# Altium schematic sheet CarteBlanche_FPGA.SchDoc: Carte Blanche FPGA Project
size A1; DrawnBy: SRKH; Engineer: SRKH; DocumentNumber: 1; Revision: CB500E; SheetNumber: 1; SheetTotal: 1
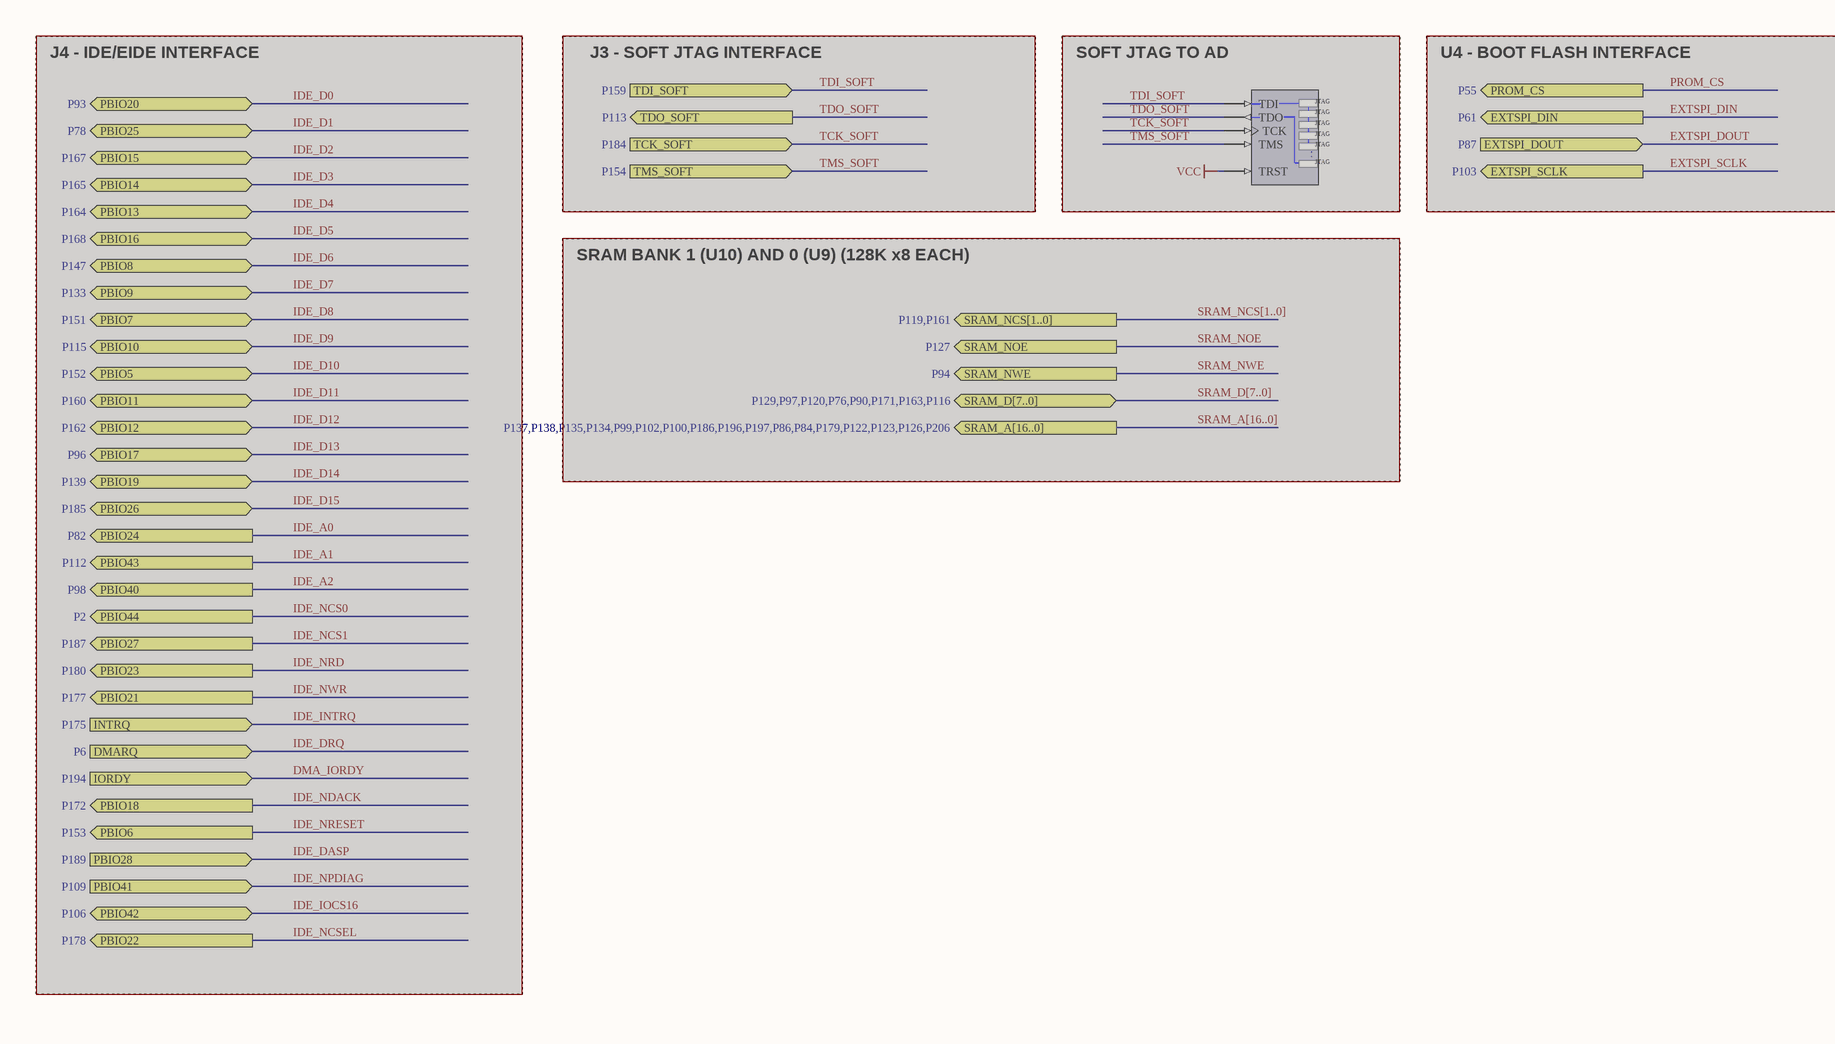
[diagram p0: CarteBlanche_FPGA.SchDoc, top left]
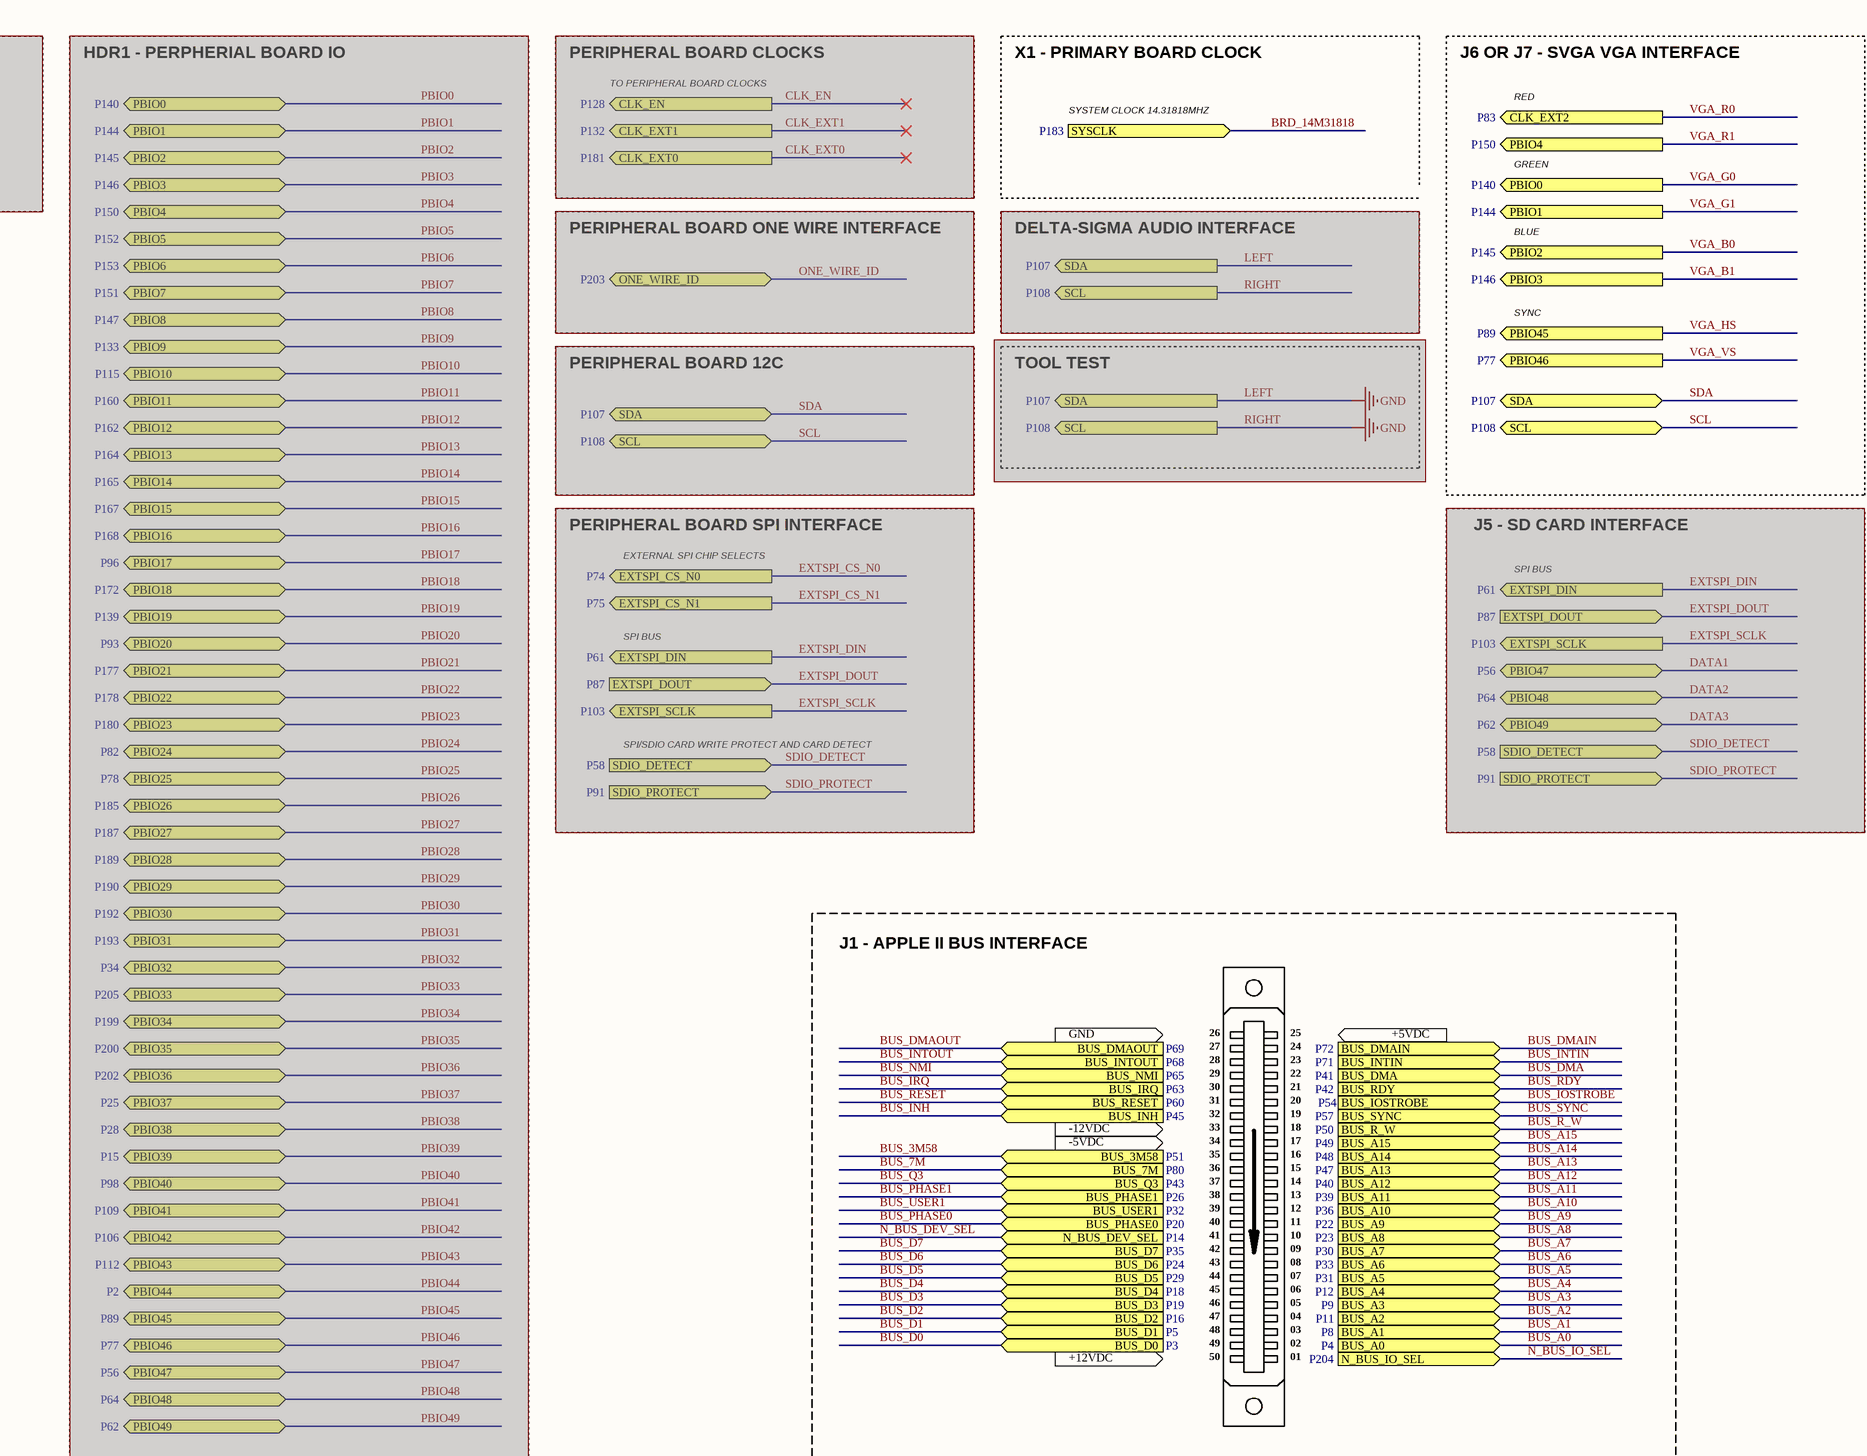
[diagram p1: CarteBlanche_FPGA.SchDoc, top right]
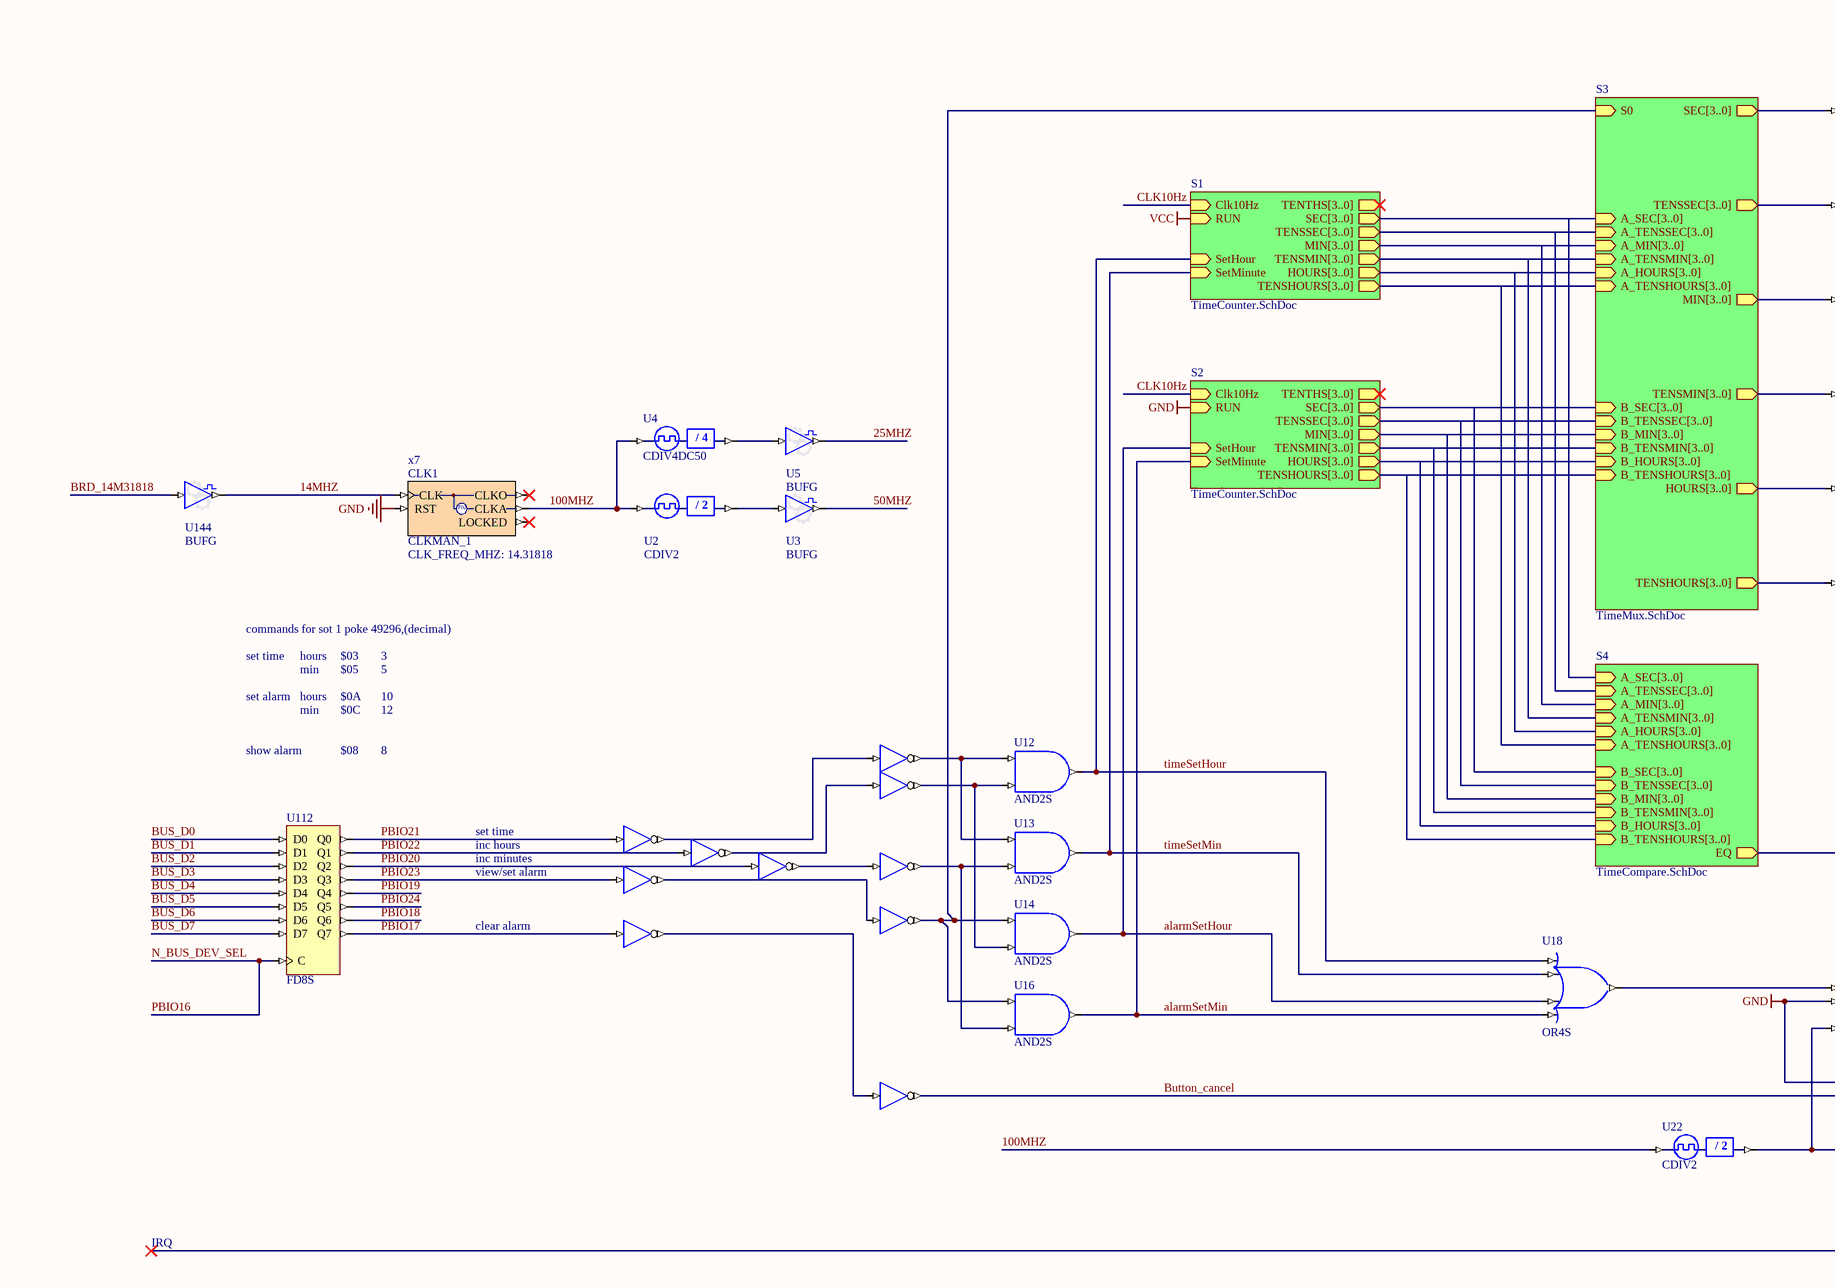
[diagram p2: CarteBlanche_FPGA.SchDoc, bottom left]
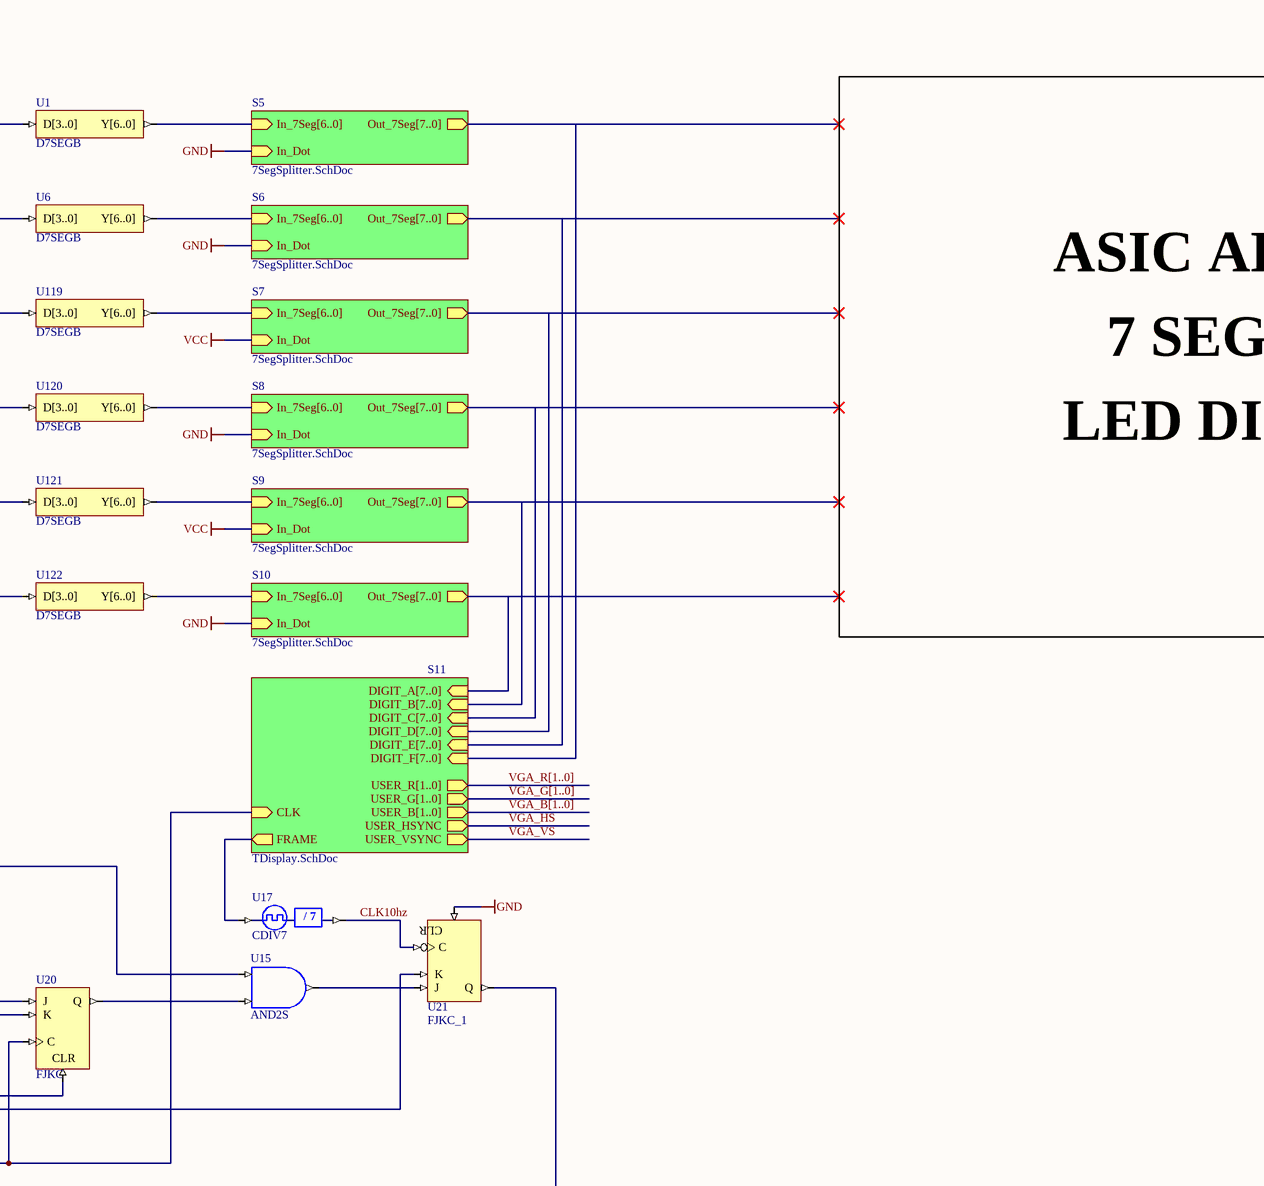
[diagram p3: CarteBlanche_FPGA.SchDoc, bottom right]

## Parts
CLK1  CLKMAN_1  CLK_FREQ_MHZ: 14.31818  ClkA_Operation: x7
NEXUS_JTAG_PORT  NEXUS_JTAG_PORT  (value not drawn)  (masked out: inside a compile mask, not in the netlist)
U1  D7SEGB
U2  CDIV2
U3  BUFG
U4  CDIV4DC50
U5  BUFG
U6  D7SEGB
U7  INV  (value not drawn)
U8  INV  (value not drawn)
U9  INV  (value not drawn)
U10  INV  (value not drawn)
U11  INV  (value not drawn)
U12  AND2S
U13  AND2S
U14  AND2S
U15  AND2S
U16  AND2S
U17  CDIV7
U18  OR4S
U19  INV  (value not drawn)
U20  FJKC
U21  FJKC_1
U22  CDIV2
U23  INV  (value not drawn)
U24  INV  (value not drawn)
U25  INV  (value not drawn)
U26  INV  (value not drawn)
U112  FD8S
U119  D7SEGB
U120  D7SEGB
U121  D7SEGB
U122  D7SEGB
U144  BUFG

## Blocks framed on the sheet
SOFT JTAG TO AD: NEXUS_JTAG_PORT

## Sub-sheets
S1 = TimeCounter.SchDoc: SetHour (in), SetMinute (in), Clk10Hz (in), SEC[3..0] (out), TENSSEC[3..0] (out), MIN[3..0] (out), TENSMIN[3..0] (out), HOURS[3..0] (out), TENSHOURS[3..0] (out), RUN (in), TENTHS[3..0] (out)
S2 = TimeCounter.SchDoc: SetHour (in), SetMinute (in), Clk10Hz (in), SEC[3..0] (out), TENSSEC[3..0] (out), MIN[3..0] (out), TENSMIN[3..0] (out), HOURS[3..0] (out), TENSHOURS[3..0] (out), RUN (in), TENTHS[3..0] (out)
S3 = TimeMux.SchDoc: SEC[3..0] (out), TENSSEC[3..0] (out), MIN[3..0] (out), TENSMIN[3..0] (out), HOURS[3..0] (out), TENSHOURS[3..0] (out), A_SEC[3..0] (in), A_TENSSEC[3..0] (in), A_MIN[3..0] (in), A_TENSMIN[3..0] (in), A_HOURS[3..0] (in), A_TENSHOURS[3..0] (in), B_SEC[3..0] (in), B_TENSSEC[3..0] (in), B_MIN[3..0] (in), B_TENSMIN[3..0] (in), B_HOURS[3..0] (in), B_TENSHOURS[3..0] (in), S0 (in)
S4 = TimeCompare.SchDoc: A_MIN[3..0] (in), A_TENSMIN[3..0] (in), A_HOURS[3..0] (in), A_TENSHOURS[3..0] (in), B_MIN[3..0] (in), B_TENSMIN[3..0] (in), B_HOURS[3..0] (in), B_TENSHOURS[3..0] (in), A_SEC[3..0] (in), A_TENSSEC[3..0] (in), B_SEC[3..0] (in), B_TENSSEC[3..0] (in), EQ (out)
S5 = 7SegSplitter.SchDoc: In_7Seg[6..0] (in), In_Dot (in), Out_7Seg[7..0] (out)
S6 = 7SegSplitter.SchDoc: In_7Seg[6..0] (in), In_Dot (in), Out_7Seg[7..0] (out)
S7 = 7SegSplitter.SchDoc: In_7Seg[6..0] (in), In_Dot (in), Out_7Seg[7..0] (out)
S8 = 7SegSplitter.SchDoc: In_7Seg[6..0] (in), In_Dot (in), Out_7Seg[7..0] (out)
S9 = 7SegSplitter.SchDoc: In_7Seg[6..0] (in), In_Dot (in), Out_7Seg[7..0] (out)
S10 = 7SegSplitter.SchDoc: In_7Seg[6..0] (in), In_Dot (in), Out_7Seg[7..0] (out)
S11 = TDisplay.SchDoc: CLK (in), FRAME (out), USER_R[1..0] (out), USER_G[1..0] (out), USER_B[1..0] (out), USER_HSYNC (out), USER_VSYNC (out), DIGIT_A[7..0] (in), DIGIT_B[7..0] (in), DIGIT_C[7..0] (in), DIGIT_D[7..0] (in), DIGIT_E[7..0] (in), DIGIT_F[7..0] (in)

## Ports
BUS_3M58 (in, see P51), BUS_7M (in, see P80), BUS_A0 (in, see P4), BUS_A1 (in, see P8), BUS_A2 (in, see P11), BUS_A3 (in, see P9), BUS_A4 (in, see P12), BUS_A5 (in, see P31), BUS_A6 (in, see P33), BUS_A7 (in, see P30), BUS_A8 (in, see P23), BUS_A9 (in, see P22), BUS_A10 (in, see P36), BUS_A11 (in, see P39), BUS_A12 (in, see P40), BUS_A13 (in, see P47), BUS_A14 (in, see P48), BUS_A15 (in, see P49), BUS_D0 (in, see P3), BUS_D1 (in, see P5), BUS_D2 (in, see P16), BUS_D3 (in, see P19), BUS_D4 (in, see P18), BUS_D5 (in, see P29), BUS_D6 (in, see P24), BUS_D7 (in, see P35), BUS_DMA (in, see P41), BUS_DMAIN (in, see P72), BUS_DMAOUT (in, see P69), BUS_INH (in, see P45), BUS_INTIN (in, see P71), BUS_INTOUT (in, see P68), BUS_IOSTROBE (in, see P54), BUS_IRQ (in, see P63), BUS_NMI (in, see P65), BUS_PHASE0 (in, see P20), BUS_PHASE1 (in, see P26), BUS_Q3 (in, see P43), BUS_R_W (in, see P50), BUS_RDY (in, see P42), BUS_RESET (in, see P60), BUS_SYNC (in, see P57), BUS_USER1 (in, see P32), CLK_EN (out, see P128), CLK_EXT0 (out, see P181), CLK_EXT1 (out, see P132), CLK_EXT2 (out, see P83), DMARQ (in, see P6), EXTSPI_CS_N0 (out, see P74), EXTSPI_CS_N1 (out, see P75), EXTSPI_DIN (out, see P61), EXTSPI_DOUT (in, see P87), EXTSPI_SCLK (out, see P103), INTRQ (in, see P175), IORDY (in, see P194), N_BUS_DEV_SEL (in, see P14), N_BUS_IO_SEL (in, see P204), ONE_WIRE_ID (bidir, see P203), PBIO0 (bidir, see P140), PBIO0 (out, see P140), PBIO1 (bidir, see P144), PBIO1 (out, see P144), PBIO2 (bidir, see P145), PBIO2 (out, see P145), PBIO3 (bidir, see P146), PBIO3 (out, see P146), PBIO4 (bidir, see P150), PBIO4 (out, see P150), PBIO5 (bidir, see P152), PBIO6 (bidir, see P153), PBIO6 (out, see P153), PBIO7 (bidir, see P151), PBIO8 (bidir, see P147), PBIO9 (bidir, see P133), PBIO10 (bidir, see P115), PBIO11 (bidir, see P160), PBIO12 (bidir, see P162), PBIO13 (bidir, see P164), PBIO14 (bidir, see P165), PBIO15 (bidir, see P167), PBIO16 (bidir, see P168), PBIO17 (bidir, see P96), PBIO18 (bidir, see P172), PBIO18 (out, see P172), PBIO19 (bidir, see P139), PBIO20 (bidir, see P93), PBIO21 (bidir, see P177), PBIO21 (out, see P177), PBIO22 (bidir, see P178), PBIO22 (out, see P178), PBIO23 (bidir, see P180), PBIO23 (out, see P180), PBIO24 (bidir, see P82), PBIO24 (out, see P82), PBIO25 (bidir, see P78), PBIO26 (bidir, see P185), PBIO27 (bidir, see P187), PBIO27 (out, see P187), PBIO28 (bidir, see P189), PBIO28 (in, see P189), PBIO29 (bidir, see P190), PBIO30 (bidir, see P192), PBIO31 (bidir, see P193), PBIO32 (bidir, see P34), PBIO33 (bidir, see P205), PBIO34 (bidir, see P199), PBIO35 (bidir, see P200), PBIO36 (bidir, see P202), PBIO37 (bidir, see P25), PBIO38 (bidir, see P28), PBIO39 (bidir, see P15), PBIO40 (bidir, see P98), PBIO40 (out, see P98), PBIO41 (bidir, see P109), PBIO41 (in, see P109), PBIO42 (bidir, see P106), PBIO43 (bidir, see P112), PBIO43 (out, see P112), PBIO44 (bidir, see P2), PBIO44 (out, see P2), PBIO45 (bidir, see P89), PBIO45 (out, see P89), PBIO46 (bidir, see P77), PBIO46 (out, see P77), PBIO47 (bidir, see P56), PBIO48 (bidir, see P64), PBIO49 (bidir, see P62), PROM_CS (out, see P55), SCL (bidir, see P108), SCL (out, see P108), SDA (bidir, see P107), SDA (out, see P107), SDIO_DETECT (in, see P58), SDIO_PROTECT (in, see P91), SRAM_A[16..0] (out, see P137,P138,P135,P134,P99,P102,P100,P186,P196,P197,P86,P84,P179,P122,P123,P126,P206), SRAM_D[7..0] (bidir, see P129,P97,P120,P76,P90,P171,P163,P116), SRAM_NCS[1..0] (out, see P119,P161), SRAM_NOE (out, see P127), SRAM_NWE (out, see P94), SYSCLK (in, see P183), TCK_SOFT (in, see P184), TDI_SOFT (in, see P159), TDO_SOFT (out, see P113), TMS_SOFT (in, see P154)

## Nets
GND: CLK1.RST U20.CLR U20.K U21.CLR ; sheet S2/RUN, sheet S5/In_Dot, sheet S6/In_Dot, sheet S8/In_Dot, sheet S10/In_Dot
VCC: sheet S1/RUN, sheet S7/In_Dot, sheet S9/In_Dot
14MHZ: CLK1.CLK U144.O
25MHZ: U5.O
50MHZ: U3.O
100MHZ: CLK1.CLKA U2.CLKIN U4.CLKIN U22.CLKIN
alarmSetHour: U14.O U18.I2 ; sheet S2/SetHour
alarmSetMin: U16.O U18.I3 ; sheet S2/SetMinute
BRD_14M31818: U144.I ; port SYSCLK
BUS_D0: U112.D0 ; port BUS_D0
BUS_D1: U112.D1 ; port BUS_D1
BUS_D2: U112.D2 ; port BUS_D2
BUS_D3: U112.D3 ; port BUS_D3
BUS_D4: U112.D4 ; port BUS_D4
BUS_D5: U112.D5 ; port BUS_D5
BUS_D6: U112.D6 ; port BUS_D6
BUS_D7: U112.D7 ; port BUS_D7
Button_cancel: U11.O U21.K
CLK10Hz: U17.CLKDV U21.C ; sheet S1/Clk10Hz, sheet S2/Clk10Hz
N_BUS_DEV_SEL: U112.C ; port N_BUS_DEV_SEL  [also labelled PBIO16]
PBIO17: U26.I U112.Q7
PBIO18: U112.Q6
PBIO19: U112.Q4
PBIO20: U24.I U112.Q2
PBIO21: U19.I U112.Q0
PBIO22: U23.I U112.Q1
PBIO23: U25.I U112.Q3
PBIO24: U112.Q5
timeSetHour: U12.O U18.I0 ; sheet S1/SetHour
timeSetMin: U13.O U18.I1 ; sheet S1/SetMinute
VGA_HS: port PBIO45, sheet S11/USER_HSYNC
VGA_VS: port PBIO46, sheet S11/USER_VSYNC
NetU2_CLKDV: U2.CLKDV U3.I
NetU4_CLKDV: U4.CLKDV U5.I
NetU7_I: U7.I U19.O
NetU7_O: U7.O U12.I0 U13.I0
NetU8_I: U8.I U23.O
NetU8_O: U8.O U12.I1 U14.I1
NetU9_I: U9.I U24.O
NetU9_O: U9.O U13.I1 U16.I1
NetU10_I: U10.I U25.O
NetU10_O: U10.O U14.I0 U16.I0 ; sheet S3/S0
NetU11_I: U11.I U26.O
NetU15_I0: U15.I0 ; sheet S4/EQ
NetU15_I1: U15.I1 U20.Q
NetU15_O: U15.O U21.J
NetU17_CLKIN: U17.CLKIN ; sheet S11/FRAME
NetU18_O: U18.O U20.J
NetU20_C: U20.C U22.CLKDV ; sheet S11/CLK

Not connected (* = marked no-connect by the designer): CLK1 CLKO* LOCKED*; U1 D[3..0] Y[6..0]; U6 D[3..0] Y[6..0]; U21 Q*; U119 D[3..0] Y[6..0]; U120 D[3..0] Y[6..0]; U121 D[3..0] Y[6..0]; U122 D[3..0] Y[6..0]

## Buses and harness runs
bus sheet S1/HOURS[3..0] = sheet S3/A_HOURS[3..0] = sheet S4/A_HOURS[3..0]
bus sheet S1/MIN[3..0] = sheet S3/A_MIN[3..0] = sheet S4/A_MIN[3..0]
bus sheet S1/SEC[3..0] = sheet S3/A_SEC[3..0] = sheet S4/A_SEC[3..0]
bus sheet S1/TENSHOURS[3..0] = sheet S3/A_TENSHOURS[3..0] = sheet S4/A_TENSHOURS[3..0]
bus sheet S1/TENSMIN[3..0] = sheet S3/A_TENSMIN[3..0] = sheet S4/A_TENSMIN[3..0]
bus sheet S1/TENSSEC[3..0] = sheet S3/A_TENSSEC[3..0] = sheet S4/A_TENSSEC[3..0]
bus sheet S2/HOURS[3..0] = sheet S3/B_HOURS[3..0] = sheet S4/B_HOURS[3..0]
bus sheet S2/MIN[3..0] = sheet S3/B_MIN[3..0] = sheet S4/B_MIN[3..0]
bus sheet S2/SEC[3..0] = sheet S3/B_SEC[3..0] = sheet S4/B_SEC[3..0]
bus sheet S2/TENSHOURS[3..0] = sheet S3/B_TENSHOURS[3..0] = sheet S4/B_TENSHOURS[3..0]
bus sheet S2/TENSMIN[3..0] = sheet S3/B_TENSMIN[3..0] = sheet S4/B_TENSMIN[3..0]
bus sheet S2/TENSSEC[3..0] = sheet S3/B_TENSSEC[3..0] = sheet S4/B_TENSSEC[3..0]
bus sheet S5/Out_7Seg[7..0] = sheet S11/DIGIT_F[7..0]
bus sheet S6/Out_7Seg[7..0] = sheet S11/DIGIT_E[7..0]
bus sheet S7/Out_7Seg[7..0] = sheet S11/DIGIT_D[7..0]
bus sheet S8/Out_7Seg[7..0] = sheet S11/DIGIT_C[7..0]
bus sheet S9/Out_7Seg[7..0] = sheet S11/DIGIT_B[7..0]
bus sheet S10/Out_7Seg[7..0] = sheet S11/DIGIT_A[7..0]
bus VGA_B[1..0] = sheet S11/USER_B[1..0]
bus VGA_G[1..0] = sheet S11/USER_G[1..0]
bus VGA_R[1..0] = sheet S11/USER_R[1..0]

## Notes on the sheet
- J4 - IDE/EIDE INTERFACE
- J3 - SOFT JTAG INTERFACE
- U4 - BOOT FLASH INTERFACE
- HDR1 - PERPHERIAL BOARD IO
- PERIPHERAL BOARD CLOCKS
- X1 - PRIMARY BOARD CLOCK
- J6 OR J7 - SVGA VGA INTERFACE
- TO PERIPHERAL BOARD CLOCKS
- SYSTEM CLOCK 14.31818MHZ
- RED
- GREEN
- SRAM BANK 1 (U10) AND 0 (U9) (128K x8 EACH)
- PERIPHERAL BOARD ONE WIRE INTERFACE
- DELTA-SIGMA AUDIO INTERFACE
- BLUE
- SYNC
- PERIPHERAL BOARD 12C
- TOOL TEST
- PERIPHERAL BOARD SPI INTERFACE
- J5 - SD CARD INTERFACE
- EXTERNAL SPI CHIP SELECTS
- SPI BUS
- SPI/SDIO CARD WRITE PROTECT AND CARD DETECT
- J1 - APPLE II BUS INTERFACE
- GND
- 26
- 27
- 28
- 29
- 25
- 24
- 23
- 22
- +5VDC
- -12VDC
- 30
- 31
- 32
- 33
- 34
- 21
- 20
- 19
- 18
- 17
- -5VDC
- 35
- 36
- 37
- 38
- 39
- 16
- 15
- 14
- 13
- 12
- 40
- 41
- 42
- 43
- 44
- 11
- 10
- 09
- 08
- 07
- 45
- 46
- 47
- 48
- 49
- 06
- 05
- 04
- 03
- 02
- +12VDC
- 50
- 01
- ASIC ADAPTOR
- 7 SEGMENT
- LED DISPLAYS
- commands for sot 1 poke 49296,(decimal)
- set time
- set alarm
- hours
- min
- $05
- $03
- $0A
- 3
- 5
- show alarm
- $0C
- $08
- 8
- inc hours
- inc minutes
- view/set alarm
- clear alarm
- IRQ

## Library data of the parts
CLK1 = CLKMAN_1: Single Operational Output Clock Manager; Clk_Count: 1
NEXUS_JTAG_PORT = NEXUS_JTAG_PORT: Soft Nexus-Chain Connector; NEXUS_JTAG_CONNECTOR: True
U1 U6 U119-U122 = D7SEGB: 7-Segment-Display Decoder for Common-Cathode LED (Active High Output), Bus Version; ArchiveName: GENERIC; VHDLIB_SIM: GENERIC_LIB
U2 U22 = CDIV2: Clock Divider by 2; DivisorRate: 2; ArchiveName: GENERIC; VHDLIB_SIM: GENERIC_LIB
U3 U5 U144 = BUFG: Configurable Global Clock Buffer; ConfiguratorName: GENERIC_BUFFER; ConfigurationParameters: {}Version[1.1]{}SignalCount[1]{}SignalWidth0[1]{}OutputOption0[Global Clock]{}EnableMode[None]{}ShowPinNames[False]{}
U4 = CDIV4DC50: Clock Divider by 4 with 50% Duty Cycle Output; DivisorRate: 4; ArchiveName: GENERIC; VHDLIB_SIM: GENERIC_LIB; XilinxEquivalent: CLK_DIV4; DutyCycle: 50
U7-U11 U19 U23-U26 = INV: Inverter; ArchiveName: GENERIC; VHDLIB_SIM: GENERIC_LIB
U12-U16 = AND2S: 2-Input AND Gate, Single Pin Version; Xilinx Equivalent: AND2; ArchiveName: GENERIC; VHDLIB_SIM: GENERIC_LIB
U17 = CDIV7: Clock Divider by 7; ArchiveName: GENERIC; VHDLIB_SIM: GENERIC_LIB
U18 = OR4S: 4-Input OR Gate, Single Pin Version; Xilinx Equivalent: OR4; ArchiveName: GENERIC; VHDLIB_SIM: GENERIC_LIB
U20 = FJKC: J-K Flip-Flop with Asynchronous Clear; ArchiveName: GENERIC; VHDLIB_SIM: GENERIC_LIB
U21 = FJKC_1: J-K Negative Edge Flip-Flop with Asynchronous Clear; ArchiveName: GENERIC; VHDLIB_SIM: GENERIC_LIB
U112 = FD8S: 8-Bit D-Type Flip-Flop, Single Pin Version; SubClass: FD; ClockTrigger: Rising; PortSize: 8; ArchiveName: GENERIC; VHDLIB_SIM: GENERIC_LIB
